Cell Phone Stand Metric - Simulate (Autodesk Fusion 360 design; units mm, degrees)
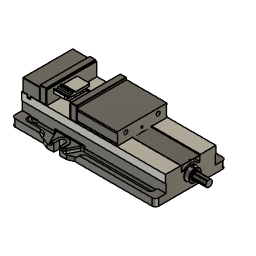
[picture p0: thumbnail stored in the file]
description: HaasClamp
derived_base_feature "Derived Base Feature" bodies "Stand Body"
align "Align1"
base_feature "Base Feature1"
base_feature "Base Feature1"
base_feature "Base Feature1"
base_feature "Base Feature1"
base_feature "Base Feature1"
base_feature "Base Feature1"
base_feature "Base Feature1"
base_feature "Base Feature1"
base_feature "Base Feature1"
base_feature "Base Feature1"
as_built_joint "As-built1"
as_built_joint "As-built2"
as_built_joint "As-built3"
joint_origin "JointOrigin1" OffsetX 0 OffsetY 0 OffsetZ 0 AngleZ 0
joint "Assemble1" alignAngle 180 alignOffsetX 0 alignOffsetY 0 alignOffsetZ 0 (= "jaw_width_haas_050002") SlideMaximum 22.5 SlideMinimum 0
position "Position1"
sketch "Sketch1" plane through (0, -72.5, 0) normal (0, -1, 0) x axis (1, 0, 0)
  line L1 (75, 73) -> (-75, 73)
  line L2 (76, 74) -> (75, 73)
  line L3 (76, 116.5) -> (76, 74)
  line L4 (75, 117.5) -> (76, 116.5)
  line L5 (-75, 117.5) -> (75, 117.5)
  line L6 (-76, 116.5) -> (-75, 117.5)
  line L7 (-76, 74) -> (-76, 116.5)
  line L8 (-75, 73) -> (-76, 74)
  line L9 (76.4, 114.275) -> (-76, 114.275)
  line L10 (76.4, 73) -> (76.4, 114.275)
  line L11 (-76, 73) -> (76.4, 73)
  line L12 (-76, 114.275) -> (-76, 73)
  circle C1 centre (49.21, 96.8) radius 11
  circle C2 centre (-49.21, 96.8) radius 11
  point P14 (76.4, 73)
  point P12 (-76, 114.275)
  point P13 (76.4, 114.275)
  horizontal L9
  vertical L10
  horizontal L11
  vertical L12
  coincident L1 P14
  coincident L7 P12
  dimension "d16" distance P12 P13 = 152.4
  dimension "d17" distance P13 P14 = 41.275
place_component sketch "Sketch1"
extrude "Extrude1" new body sketch "Sketch1" profile of L1 L2 L3 L7 L8 C1 C2 L9 L11 L12 along normal blind 3.175
place_component sketch "Sketch1"
extrude "Extrude1" sketch "Sketch1" profile of L1 L2 L3 L7 L8 C1 C2 L9 L11 L12 blind -3.175
as_built_joint "As-built5"
as_built_joint "As-built6"
sketch "Sketch1" plane through (0, 0, 0) normal (0, 0, -1) x axis (1, 0, 0)
  line L1 (16.5, -37.5) -> (-16.5, -37.5)
  line L2 (20, 34) -> (20, -34)
  line L3 (-16.5, 37.5) -> (16.5, 37.5)
  line L4 (-20, -34) -> (-20, 34)
  line L5 (-38.1, -40) -> (38.1, -40)
  line L6 (-38.1, 40) -> (-38.1, -40)
  line L7 (38.1, 40) -> (-38.1, 40)
  line L8 (38.1, -40) -> (38.1, 40)
  line L9 (-38.1, 40) -> (38.1, -40)
  line L10 (38.1, 40) -> (-38.1, -40)
  arc A1 centre (-16.5, -34) radius 3.5 clockwise from (-16.5, -37.5) to (-20, -34)
  arc A2 centre (16.5, -34) radius 3.5 clockwise from (20, -34) to (16.5, -37.5)
  arc A3 centre (16.5, 34) radius 3.5 clockwise from (16.5, 37.5) to (20, 34)
  arc A4 centre (-16.5, 34) radius 3.5 clockwise from (-20, 34) to (-16.5, 37.5)
  point P18 (0, 0)
  point P1 (0, 0)
  point P16 (-38.1, 40)
  point P17 (38.1, 40)
  point P15 (-38.1, -40)
  horizontal L5
  perpendicular L5 L6
  parallel L5 L7
  parallel L6 L8
  coincident L9 P18
  coincident L10 P18
  coincident P1 P18
  dimension "d1" distance P16 P17 = 76.2
  dimension "d2" distance P15 P16 = 80
extrude "Extrude1" new body sketch "Sketch1" profile of A1 L1 A2 L2 A3 L3 A4 L4 L5 L6 L7 L8 against normal blind 10 bodies "Stock"
position "Position1"
ground "Pin"
position "Position2"
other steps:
create_component "CreateComponent1"
create_component "CreateComponent2"
create_component "CreateComponent3"
create_component "CreateComponent4"
create_component "CreateComponent5"
create_component "CreateComponent6"
create_component "CreateComponent7"
create_component "CreateComponent8"
create_component "CreateComponent9"
create_component "CreateComponent10"
joint_origin "JointOrigin10"
joint_origin "JointOrigin11"
create_component "CreateComponent11" sketch "Sketch1"
create_component "CreateComponent12" sketch "Sketch1"
create_component "CreateComponent1"
named bodies: "Stand Body", "Stock"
